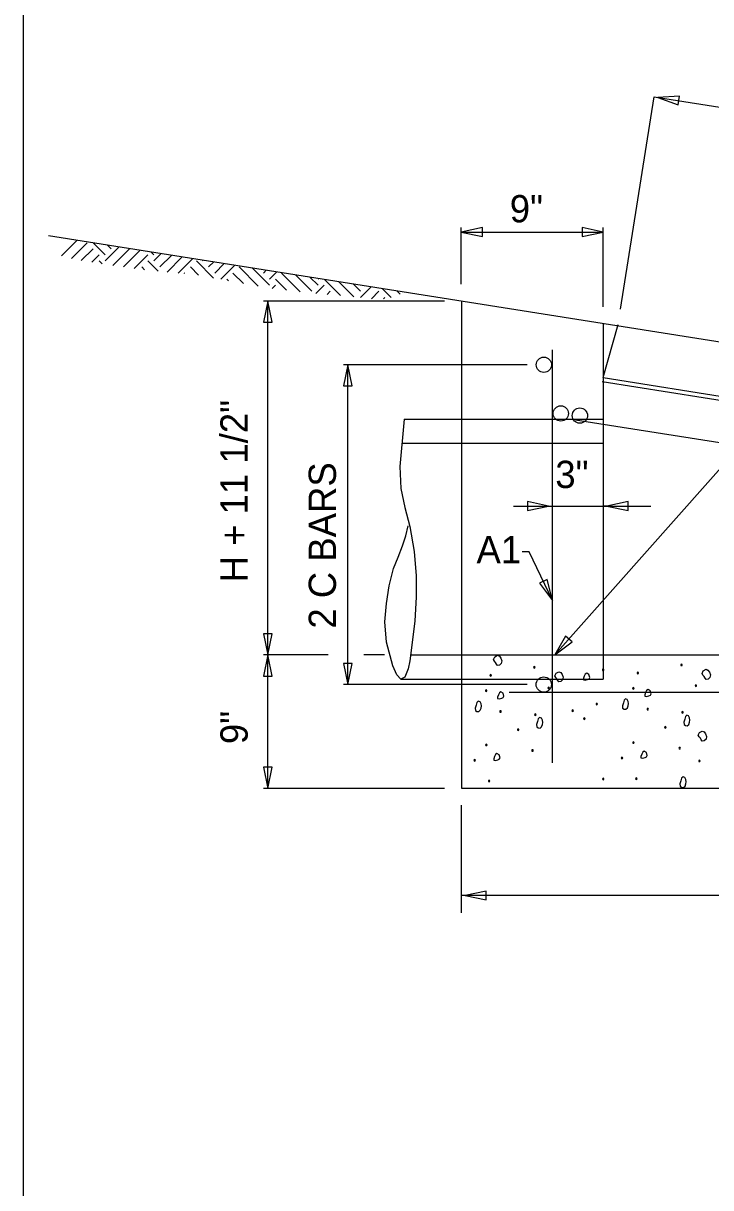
# Model space of a CAD drawing. Extents: x -439.1 to -407.9, y -458.1 to -436.2.
# Drawn here: x -439.11 to -435.33, y -451.36 to -444.97 of the extents above; entities that cross this region are included whole.
import ezdxf

# ---------------------------------------------------------------- set-up
doc = ezdxf.new("R2010")
doc.units = 0
for name, color, linetype in [('Bridge-Named Boundary', 7, 'Continuous'), ('Level 4', 7, 'Continuous'), ('Level 45', 7, 'Continuous')]:
    doc.layers.add(name, color=color, linetype=linetype)

msp = doc.modelspace()

# ---------------------------------------------------------------- linework, layer by layer
at = {"layer": 'Bridge-Named Boundary'}
msp.add_lwpolyline([(-439.109, -458.0508), (-407.859, -458.0508), (-407.859, -437.6758), (-439.109, -437.6758)], close=True, dxfattribs=at)
at = {"layer": 'Level 4'}
for p, q in [((-435.828, -446.5379), (-435.643, -445.37)), ((-435.643, -445.37), (-430.4863, -446.1867)), ((-436.7024, -446.4006), (-436.7024, -446.0892)), ((-436.7024, -446.1133), (-435.9227, -446.1133)), ((-435.9227, -446.5241), (-435.9227, -446.0892)), ((-438.971, -446.1333), (-425.1939, -448.3149)), ((-438.8989, -446.245), (-438.8124, -446.1585)), ((-438.8449, -446.2579), (-438.7589, -446.1719)), ((-438.6587, -446.2387), (-438.725, -446.1724)), ((-438.6587, -446.2721), (-438.5817, -446.1951)), ((-438.6253, -446.2053), (-438.6456, -446.185)), ((-438.7907, -446.2705), (-438.7255, -446.2053)), ((-438.7329, -446.2795), (-438.6921, -446.2387)), ((-438.6171, -446.2974), (-438.524, -446.2043)), ((-438.5585, -446.3055), (-438.4663, -446.2134)), ((-438.4998, -446.3137), (-438.4248, -446.2387)), ((-438.3914, -446.2387), (-438.4073, -446.2228)), ((-438.3914, -446.2721), (-438.351, -446.2317)), ((-438.358, -446.3055), (-438.2933, -446.2409)), ((-438.3188, -446.3331), (-438.2357, -446.25)), ((-438.2574, -446.3385), (-438.178, -446.2591)), ((-438.6757, -446.2885), (-438.6921, -446.2721)), ((-438.4422, -446.3216), (-438.4582, -446.3055)), ((-438.368, -446.3289), (-438.4248, -446.2721)), ((-438.1454, -446.351), (-438.1909, -446.3055)), ((-438.0636, -446.366), (-438.1575, -446.2721)), ((-438.1241, -446.2721), (-438.1203, -446.2683)), ((-438.0907, -446.3055), (-438.0626, -446.2775)), ((-438.0573, -446.3389), (-438.005, -446.2866)), ((-438.0239, -446.3723), (-437.9473, -446.2958)), ((-437.8188, -446.4103), (-437.9236, -446.3055)), ((-437.7566, -446.4057), (-437.8514, -446.311)), ((-437.79, -446.3389), (-437.7743, -446.3232)), ((-438.2212, -446.3421), (-438.2243, -446.3389)), ((-437.9814, -446.3814), (-437.9905, -446.3723)), ((-437.8992, -446.3968), (-437.9571, -446.3389)), ((-437.7566, -446.3723), (-437.7166, -446.3324)), ((-437.6619, -446.4336), (-437.7232, -446.3723)), ((-437.5871, -446.4416), (-437.6898, -446.3389)), ((-437.5227, -446.4391), (-437.6131, -446.3488)), ((-437.4893, -446.4057), (-437.5337, -446.3614)), ((-437.4893, -446.3723), (-437.4859, -446.369)), ((-437.3654, -446.4628), (-437.4542, -446.374)), ((-437.2925, -446.4689), (-437.3748, -446.3866)), ((-437.7408, -446.4233), (-437.7232, -446.4057)), ((-437.5009, -446.4508), (-437.4559, -446.4057)), ((-437.4399, -446.4566), (-437.4225, -446.4391)), ((-437.2554, -446.4391), (-437.2954, -446.3992)), ((-437.2561, -446.4732), (-437.1976, -446.4147)), ((-437.1966, -446.4806), (-437.1552, -446.4391)), ((-437.0882, -446.4727), (-437.1365, -446.4244)), ((-437.0388, -446.4554), (-437.0571, -446.437)), ((-436.7943, -446.4924), (-437.7897, -446.4924)), ((-437.7656, -448.437), (-437.7656, -446.4924)), ((-437.1291, -446.4799), (-437.1218, -446.4726)), ((-436.7019, -446.4921), (-436.7019, -449.1696)), ((-436.1881, -448.4367), (-434.502, -446.5338)), ((-435.9228, -446.616), (-435.9228, -448.5711)), ((-435.9228, -446.9132), (-435.8409, -446.6213)), ((-436.2021, -446.7609), (-436.2021, -449.03)), ((-436.3404, -446.8428), (-437.3497, -446.8428)), ((-437.3255, -448.6), (-437.3255, -446.8428)), ((-435.9281, -446.9342), (-430.7645, -447.7516)), ((-435.9228, -446.9132), (-430.76, -447.7311)), ((-437.0171, -447.141), (-435.9228, -447.141)), ((-436.074, -447.1452), (-430.0008, -448.107)), ((-435.9228, -447.2744), (-437.0291, -447.2744)), ((-436.4157, -447.6188), (-435.6602, -447.6188)), ((-435.8992, -447.6188), (-435.9227, -447.6188)), ((-436.3285, -447.8703), (-436.3684, -447.8703)), ((-436.202, -448.1375), (-436.3285, -447.8703)), ((-437.4333, -448.437), (-437.7897, -448.437)), ((-437.7656, -449.1701), (-437.7656, -448.437)), ((-437.1243, -448.437), (-437.2381, -448.437)), ((-436.981, -448.4367), (-435.9228, -448.4367)), ((-435.9228, -448.4367), (-425.1939, -448.4367)), ((-436.3412, -448.6), (-437.3497, -448.6)), ((-437.034, -448.5711), (-435.9228, -448.5711)), ((-436.4384, -448.6425), (-430.5353, -448.6425)), ((-436.7943, -449.1701), (-437.7897, -449.1701)), ((-436.7019, -449.1696), (-425.1939, -449.1696)), ((-436.7024, -449.262), (-436.7024, -449.8535)), ((-425.1938, -449.759), (-436.7024, -449.759))]:
    msp.add_line(p, q, dxfattribs=at)
for points in [[(-435.5038, -445.3676), (-435.6223, -445.3733), (-435.5113, -445.4153)], [(-436.5862, -446.0892), (-436.7024, -446.1133), (-436.5862, -446.1374)], [(-436.0389, -446.1374), (-435.9227, -446.1133), (-436.0389, -446.0892)], [(-437.7414, -446.6086), (-437.7656, -446.4924), (-437.7897, -446.6086)], [(-437.3014, -446.959), (-437.3255, -446.8428), (-437.3497, -446.959)], [(-436.3392, -447.6429), (-436.223, -447.6188), (-436.3392, -447.5947)], [(-435.7856, -447.5947), (-435.9017, -447.6188), (-435.7856, -447.6429)], [(-436.2735, -448.0428), (-436.202, -448.1375), (-436.2299, -448.0221)], [(-437.7897, -448.3209), (-437.7656, -448.437), (-437.7414, -448.3209)], [(-436.1291, -448.3338), (-436.1881, -448.4367), (-436.093, -448.3658)], [(-437.7414, -448.5532), (-437.7656, -448.437), (-437.7897, -448.5532)], [(-437.3497, -448.4838), (-437.3255, -448.6), (-437.3014, -448.4838)], [(-436.5254, -448.4624), (-436.5188, -448.4467), (-436.5033, -448.439), (-436.4931, -448.4439), (-436.4852, -448.4546), (-436.4795, -448.4699), (-436.4826, -448.4845), (-436.4926, -448.4933), (-436.5033, -448.4949), (-436.5088, -448.4878), (-436.5137, -448.478), (-436.5207, -448.4704), (-436.5254, -448.4624)], [(-436.1884, -448.5524), (-436.1818, -448.5367), (-436.1663, -448.529), (-436.156, -448.5339), (-436.1481, -448.5446), (-436.1424, -448.5599), (-436.1455, -448.5745), (-436.1556, -448.5833), (-436.1663, -448.5849), (-436.1718, -448.5778), (-436.1767, -448.568), (-436.1837, -448.5604), (-436.1884, -448.5524)], [(-436.0133, -448.5373), (-436.0211, -448.5432), (-436.0263, -448.5541), (-436.0311, -448.5654), (-436.0315, -448.5736), (-436.022, -448.5759), (-436.0081, -448.5723), (-436.0004, -448.5675), (-435.9964, -448.5606), (-436.0007, -448.5447), (-436.0133, -448.5373)], [(-435.3795, -448.5395), (-435.3729, -448.5238), (-435.3574, -448.5161), (-435.3471, -448.521), (-435.3392, -448.5317), (-435.3335, -448.547), (-435.3366, -448.5616), (-435.3467, -448.5704), (-435.3574, -448.572), (-435.3629, -448.5649), (-435.3678, -448.5551), (-435.3748, -448.5475), (-435.3795, -448.5395)], [(-435.6763, -448.6273), (-435.6841, -448.6332), (-435.6893, -448.6441), (-435.694, -448.6554), (-435.6944, -448.6636), (-435.685, -448.6659), (-435.6711, -448.6623), (-435.6633, -448.6576), (-435.6594, -448.6506), (-435.6637, -448.6347), (-435.6763, -448.6273)], [(-436.609, -448.6903), (-436.617, -448.6977), (-436.6207, -448.7123), (-436.626, -448.7291), (-436.6246, -448.7422), (-436.6164, -448.7478), (-436.6064, -448.7487), (-436.598, -448.7413), (-436.5934, -448.7292), (-436.5916, -448.7175), (-436.5934, -448.7059), (-436.5995, -448.695), (-436.609, -448.6903)], [(-436.4852, -448.6402), (-436.493, -448.6461), (-436.4982, -448.657), (-436.5029, -448.6683), (-436.5034, -448.6765), (-436.4939, -448.6788), (-436.48, -448.6752), (-436.4722, -448.6705), (-436.4683, -448.6635), (-436.4726, -448.6476), (-436.4852, -448.6402)], [(-435.8001, -448.6774), (-435.808, -448.6848), (-435.8118, -448.6994), (-435.8171, -448.7162), (-435.8157, -448.7293), (-435.8075, -448.7349), (-435.7975, -448.7358), (-435.7891, -448.7284), (-435.7845, -448.7163), (-435.7827, -448.7046), (-435.7845, -448.6929), (-435.7906, -448.6821), (-435.8001, -448.6774)], [(-436.272, -448.7803), (-436.2799, -448.7877), (-436.2837, -448.8023), (-436.289, -448.8191), (-436.2876, -448.8322), (-436.2794, -448.8378), (-436.2694, -448.8387), (-436.261, -448.8313), (-436.2564, -448.8192), (-436.2546, -448.8075), (-436.2564, -448.7959), (-436.2624, -448.785), (-436.272, -448.7803)], [(-435.4631, -448.7674), (-435.471, -448.7748), (-435.4748, -448.7894), (-435.48, -448.8062), (-435.4786, -448.8193), (-435.4704, -448.8249), (-435.4605, -448.8258), (-435.452, -448.8184), (-435.4475, -448.8063), (-435.4457, -448.7946), (-435.4475, -448.7829), (-435.4535, -448.7721), (-435.4631, -448.7674)], [(-435.4005, -448.8785), (-435.3939, -448.8627), (-435.3785, -448.8551), (-435.3682, -448.8599), (-435.3603, -448.8707), (-435.3546, -448.8859), (-435.3577, -448.9005), (-435.3677, -448.9094), (-435.3785, -448.9109), (-435.3839, -448.9039), (-435.3888, -448.894), (-435.3958, -448.8865), (-435.4005, -448.8785)], [(-436.5063, -448.9791), (-436.514, -448.985), (-436.5192, -448.996), (-436.524, -449.0072), (-436.5244, -449.0155), (-436.5149, -449.0178), (-436.5011, -449.0142), (-436.4933, -449.0094), (-436.4894, -449.0025), (-436.4936, -448.9866), (-436.5063, -448.9791)], [(-435.6973, -448.9662), (-435.7051, -448.9721), (-435.7103, -448.9831), (-435.7151, -448.9943), (-435.7155, -449.0026), (-435.706, -449.0049), (-435.6921, -449.0013), (-435.6844, -448.9965), (-435.6805, -448.9896), (-435.6847, -448.9736), (-435.6973, -448.9662)], [(-437.7897, -449.054), (-437.7656, -449.1701), (-437.7414, -449.054)], [(-435.4841, -449.1063), (-435.4921, -449.1138), (-435.4958, -449.1284), (-435.5011, -449.1452), (-435.4997, -449.1583), (-435.4915, -449.1639), (-435.4815, -449.1647), (-435.4731, -449.1574), (-435.4686, -449.1453), (-435.4667, -449.1335), (-435.4686, -449.1219), (-435.4746, -449.1111), (-435.4841, -449.1063)], [(-436.5652, -449.7348), (-436.6814, -449.759), (-436.5652, -449.7831)]]:
    msp.add_lwpolyline(points, close=True, dxfattribs=at)
msp.add_lwpolyline([(-437.0171, -447.141), (-437.0405, -447.4012), (-437.034, -447.5231), (-437.0118, -447.6272), (-436.9851, -447.7318), (-436.9608, -447.8694), (-436.9496, -448.0027), (-436.9495, -448.117), (-436.9585, -448.2514), (-436.9849, -448.4689), (-436.9948, -448.5134), (-437.0125, -448.5595), (-437.034, -448.5711), (-437.0561, -448.5465), (-437.0787, -448.4968), (-437.1139, -448.3668), (-437.1227, -448.2546), (-437.1139, -448.1537), (-437.0988, -448.0581), (-437.0739, -447.9627), (-437.0497, -447.9003), (-437.0251, -447.8384), (-437.0079, -447.7834), (-436.994, -447.7274)], dxfattribs=at)
for centre in [(-436.2486, -446.8428), (-436.1555, -447.1104), (-436.0508, -447.1221), (-436.2493, -448.6)]:
    msp.add_circle(centre, 0.042, dxfattribs=at)
for centre, start, end in [((-435.4922, -448.4918), 0, 180), ((-435.4922, -448.4918), 180, 0), ((-436.541, -448.5492), 0, 180), ((-436.541, -448.5492), 180, 0), ((-436.3011, -448.5047), 0, 180), ((-436.3011, -448.5047), 180, 0), ((-435.9229, -448.5188), 0, 180), ((-435.9229, -448.5188), 180, 0), ((-435.7321, -448.5363), 0, 180), ((-435.7321, -448.5363), 180, 0), ((-436.2222, -448.6188), 0, 180), ((-436.2222, -448.6188), 180, 0), ((-435.7567, -448.6208), 0, 180), ((-435.7567, -448.6208), 180, 0), ((-435.4133, -448.6059), 0, 180), ((-435.4133, -448.6059), 180, 0), ((-436.5656, -448.6337), 0, 180), ((-436.5656, -448.6337), 180, 0), ((-436.4867, -448.7478), 0, 180), ((-436.4867, -448.7478), 180, 0), ((-436.0899, -448.7434), 0, 180), ((-436.0899, -448.7434), 180, 0), ((-435.9578, -448.7073), 0, 180), ((-435.9578, -448.7073), 180, 0), ((-435.6777, -448.7349), 0, 180), ((-435.6777, -448.7349), 180, 0), ((-435.487, -448.7524), 0, 180), ((-435.487, -448.7524), 180, 0), ((-436.2959, -448.7653), 0, 180), ((-436.2959, -448.7653), 180, 0), ((-436.026, -448.7869), 0, 180), ((-436.026, -448.7869), 180, 0), ((-436.3898, -448.8482), 0, 180), ((-436.3898, -448.8482), 180, 0), ((-435.5809, -448.8353), 0, 180), ((-435.5809, -448.8353), 180, 0), ((-436.5652, -448.9314), 0, 180), ((-436.5652, -448.9314), 180, 0), ((-435.7563, -448.9185), 0, 180), ((-435.7563, -448.9185), 180, 0), ((-435.502, -448.9493), 0, 180), ((-436.3109, -448.9622), 0, 180), ((-436.3109, -448.9622), 180, 0), ((-435.8196, -449.003), 0, 180), ((-435.8196, -449.003), 180, 0), ((-435.502, -448.9493), 180, 0), ((-436.6285, -449.0159), 0, 180), ((-436.6285, -449.0159), 180, 0), ((-435.3938, -449.0192), 0, 180), ((-435.3938, -449.0192), 180, 0), ((-436.5495, -449.13), 0, 180), ((-436.5495, -449.13), 180, 0), ((-435.9224, -449.1185), 0, 180), ((-435.9224, -449.1185), 180, 0), ((-435.7406, -449.1171), 0, 180), ((-435.7406, -449.1171), 180, 0)]:
    msp.add_arc(centre, 0.00416, start, end, dxfattribs=at)

# ---------------------------------------------------------------- texts
msp.add_text('2 C BARS', height=0.15, rotation=90, dxfattribs=at).set_placement((-437.3908, -448.2926))
msp.add_text('A1', height=0.15, dxfattribs=at).set_placement((-436.6188, -447.9333))
at = {"layer": 'Level 45'}
for s, p in [('9"', (-436.436, -446.0602)), ('3"', (-436.1858, -447.5199))]:
    msp.add_text(s, height=0.15, dxfattribs=at).set_placement(p)
for s, p in [('H + 11 1/2"', (-437.876, -448.0382)), ('9"', (-437.876, -448.927))]:
    msp.add_text(s, height=0.15, rotation=90, dxfattribs=at).set_placement(p)

doc.saveas('drawing.dxf')
